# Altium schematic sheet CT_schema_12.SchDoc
size 144 x 119 mm
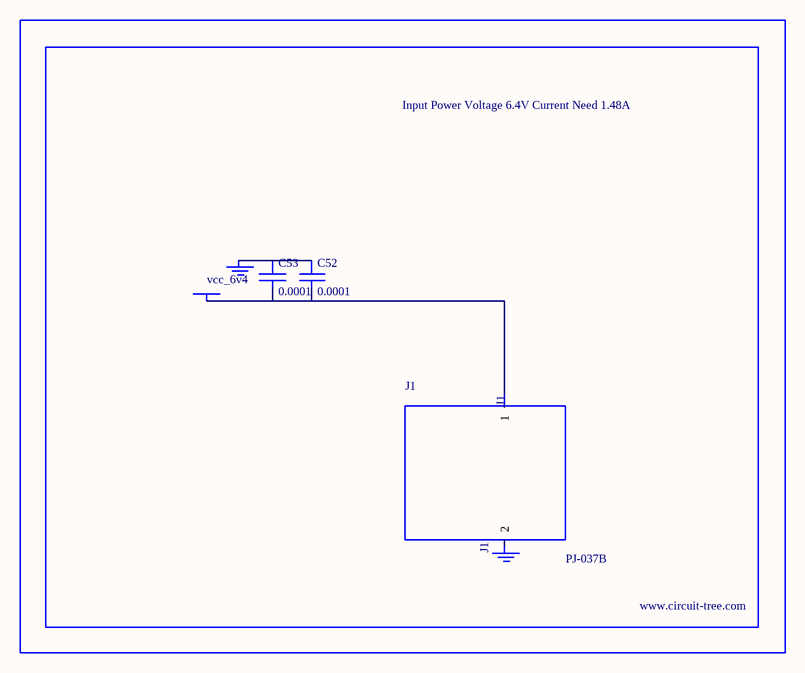
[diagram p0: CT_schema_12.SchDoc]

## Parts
BORDER11  (no value)
C52  0.0001  [EXV-9H]
C53  0.0001  [EXV-9H]
GND_INSTANCE_11_0  (no value)
GND_INSTANCE_11_1  (no value)
J1  PJ-037B  [PJ-037B_PACKAGE]
POWER_INSTANCE_11_0  vcc_6v4

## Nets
NetC52_1: C52.1 C53.1 GND_INSTANCE_11_0.0(GND)
NetC52_2: C52.2 C53.2 J1.1 POWER_INSTANCE_11_0.0(PWR)

Not connected (* = marked no-connect by the designer): GND_INSTANCE_11_1 0(GND); J1 2

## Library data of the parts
BORDER11 = BORDER_PAGE11
C52 C53 = EDK107M035A9HAA
GND_INSTANCE_11_0 GND_INSTANCE_11_1 = GND
POWER_INSTANCE_11_0 = PWR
